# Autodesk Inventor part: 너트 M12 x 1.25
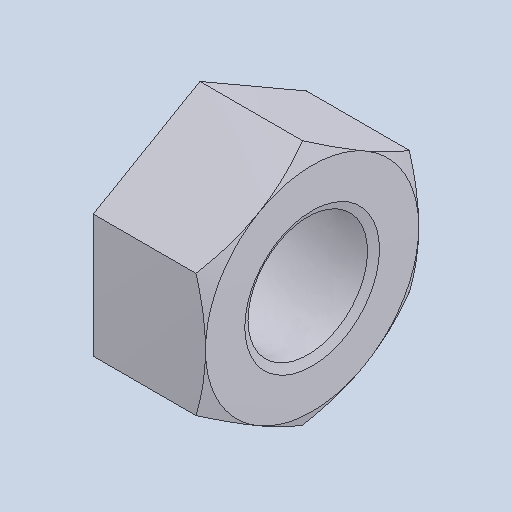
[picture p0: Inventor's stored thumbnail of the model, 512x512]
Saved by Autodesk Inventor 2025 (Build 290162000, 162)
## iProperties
Created: 2024-08
Part Number: 너트 M12 x 1.25
Material: 스테인리스강
Description: 6각 너트
Document SubType Name: Modeling
Designer: samsung
Density: 8.08 g/cm^3
Appearance: 기본값
Author: jhkim
Sending System: Autodesk Inventor 2025
Preprocessor: ST-DEVELOPER v20
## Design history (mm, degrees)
feature "Solid1"
node "솔리드1"
